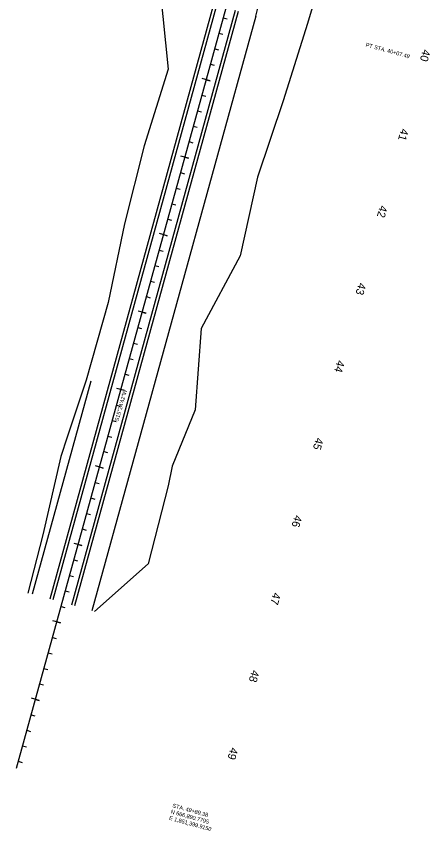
# Model space of a CAD drawing. Extents: x 1849567 to 1851966, y 666813 to 670457.
# Drawn here: x 1851400 to 1851915, y 666813 to 667827 of the extents above; entities that cross this region are included whole.
import ezdxf

# ---------------------------------------------------------------- set-up
doc = ezdxf.new("R2010")
doc.units = 0
for name, color, linetype in [('_CIVIL_CONSTRUCTION', 7, 'Continuous'), ('Default', 7, 'Continuous'), ('DES - CL - Proposed', 7, 'Continuous'), ('DES - CL - Proposed Curve Text', 7, 'Continuous'), ('DES - CL - Proposed Text', 7, 'Continuous'), ('DES - CL - Proposed Text - Large', 7, 'Continuous'), ('DES - CL - Proposed Text - Small', 7, 'Continuous'), ('DES - MODEL - Lines - Cut Slopes', 7, 'Continuous'), ('DES - MODEL - Lines - Ditch Centerline', 7, 'Continuous'), ('DES - MODEL - Lines - Pavement Edge', 7, 'Continuous'), ('DES - MODEL - Lines - Shoulder Edge', 7, 'Continuous')]:
    doc.layers.add(name, color=color, linetype=linetype)

msp = doc.modelspace()

# ---------------------------------------------------------------- linework, layer by layer
at = {"layer": '_CIVIL_CONSTRUCTION'}
msp.add_line((1851660.9, 667837.4), (1851399.9, 666890.8), dxfattribs=at)
at = {"layer": 'Default'}
msp.add_line((1851660.9, 667837.4), (1851399.9, 666890.8), dxfattribs=at)
msp.add_line((1851660.9, 667837.4), (1851399.9, 666890.8), dxfattribs=at)
at = {"layer": 'DES - CL - Proposed'}
msp.add_line((1851660.9, 667837.4), (1851399.9, 666890.8), dxfattribs=at)
at = {"layer": 'DES - CL - Proposed Text - Large'}
for p, q in [((1851636.3, 667748.2), (1851641.1, 667746.9)), ((1851636.3, 667748.2), (1851641.1, 667746.9)), ((1851609.7, 667651.8), (1851614.5, 667650.5)), ((1851609.7, 667651.8), (1851614.5, 667650.5)), ((1851583.1, 667555.4), (1851587.9, 667554)), ((1851583.1, 667555.4), (1851587.9, 667554)), ((1851556.5, 667459), (1851561.3, 667457.6)), ((1851556.5, 667459), (1851561.3, 667457.6)), ((1851534.8, 667361.2), (1851525.1, 667363.9)), ((1851534.8, 667361.2), (1851525.1, 667363.9)), ((1851503.4, 667266.2), (1851508.2, 667264.8)), ((1851503.4, 667266.2), (1851508.2, 667264.8)), ((1851476.8, 667169.8), (1851481.6, 667168.4)), ((1851476.8, 667169.8), (1851481.6, 667168.4)), ((1851450.2, 667073.4), (1851455, 667072)), ((1851450.2, 667073.4), (1851455, 667072)), ((1851423.7, 666976.9), (1851428.5, 666975.6)), ((1851423.7, 666976.9), (1851428.5, 666975.6))]:
    msp.add_line(p, q, dxfattribs=at)
at = {"layer": 'DES - CL - Proposed Text - Small'}
for p, q in [((1851657.5, 667825.3), (1851662.3, 667824)), ((1851657.5, 667825.3), (1851662.3, 667824)), ((1851652.2, 667806), (1851657, 667804.7)), ((1851652.2, 667806), (1851657, 667804.7)), ((1851646.9, 667786.7), (1851651.7, 667785.4)), ((1851646.9, 667786.7), (1851651.7, 667785.4)), ((1851641.6, 667767.5), (1851646.4, 667766.1)), ((1851641.6, 667767.5), (1851646.4, 667766.1)), ((1851641.1, 667746.9), (1851631.4, 667749.5)), ((1851641.1, 667746.9), (1851631.4, 667749.5)), ((1851631, 667728.9), (1851635.8, 667727.6)), ((1851631, 667728.9), (1851635.8, 667727.6)), ((1851625.6, 667709.6), (1851630.4, 667708.3)), ((1851625.6, 667709.6), (1851630.4, 667708.3)), ((1851620.3, 667690.3), (1851625.1, 667689)), ((1851620.3, 667690.3), (1851625.1, 667689)), ((1851615, 667671.1), (1851619.8, 667669.7)), ((1851615, 667671.1), (1851619.8, 667669.7)), ((1851614.5, 667650.4), (1851604.9, 667653.1)), ((1851614.5, 667650.4), (1851604.9, 667653.1)), ((1851604.4, 667632.5), (1851609.2, 667631.2)), ((1851604.4, 667632.5), (1851609.2, 667631.2)), ((1851599.1, 667613.2), (1851603.9, 667611.9)), ((1851599.1, 667613.2), (1851603.9, 667611.9)), ((1851593.7, 667593.9), (1851598.5, 667592.6)), ((1851593.7, 667593.9), (1851598.5, 667592.6)), ((1851588.4, 667574.7), (1851593.2, 667573.3)), ((1851588.4, 667574.7), (1851593.2, 667573.3)), ((1851587.9, 667554), (1851578.3, 667556.7)), ((1851587.9, 667554), (1851578.3, 667556.7)), ((1851577.8, 667536.1), (1851582.6, 667534.8)), ((1851577.8, 667536.1), (1851582.6, 667534.8)), ((1851572.5, 667516.8), (1851577.3, 667515.5)), ((1851572.5, 667516.8), (1851577.3, 667515.5)), ((1851567.2, 667497.5), (1851572, 667496.2)), ((1851567.2, 667497.5), (1851572, 667496.2)), ((1851561.9, 667478.2), (1851566.7, 667476.9)), ((1851561.9, 667478.2), (1851566.7, 667476.9)), ((1851561.4, 667457.6), (1851551.7, 667460.3)), ((1851561.4, 667457.6), (1851551.7, 667460.3)), ((1851551.2, 667439.7), (1851556, 667438.4)), ((1851551.2, 667439.7), (1851556, 667438.4)), ((1851545.9, 667420.4), (1851550.7, 667419.1)), ((1851545.9, 667420.4), (1851550.7, 667419.1)), ((1851540.6, 667401.1), (1851545.4, 667399.8)), ((1851540.6, 667401.1), (1851545.4, 667399.8)), ((1851535.3, 667381.8), (1851540.1, 667380.5)), ((1851535.3, 667381.8), (1851540.1, 667380.5)), ((1851534.8, 667361.2), (1851525.1, 667363.9)), ((1851534.8, 667361.2), (1851525.1, 667363.9)), ((1851524.7, 667343.3), (1851529.5, 667342)), ((1851524.7, 667343.3), (1851529.5, 667342)), ((1851519.3, 667324), (1851524.1, 667322.7)), ((1851519.3, 667324), (1851524.1, 667322.7)), ((1851514, 667304.7), (1851518.8, 667303.4)), ((1851514, 667304.7), (1851518.8, 667303.4)), ((1851508.7, 667285.4), (1851513.5, 667284.1)), ((1851508.7, 667285.4), (1851513.5, 667284.1)), ((1851508.2, 667264.8), (1851498.6, 667267.5)), ((1851508.2, 667264.8), (1851498.6, 667267.5)), ((1851498.1, 667246.9), (1851502.9, 667245.6)), ((1851498.1, 667246.9), (1851502.9, 667245.6)), ((1851492.8, 667227.6), (1851497.6, 667226.3)), ((1851492.8, 667227.6), (1851497.6, 667226.3)), ((1851487.4, 667208.3), (1851492.2, 667207)), ((1851487.4, 667208.3), (1851492.2, 667207)), ((1851482.1, 667189), (1851486.9, 667187.7)), ((1851482.1, 667189), (1851486.9, 667187.7)), ((1851481.6, 667168.4), (1851472, 667171.1)), ((1851481.6, 667168.4), (1851472, 667171.1)), ((1851471.5, 667150.5), (1851476.3, 667149.2)), ((1851471.5, 667150.5), (1851476.3, 667149.2)), ((1851466.2, 667131.2), (1851471, 667129.9)), ((1851466.2, 667131.2), (1851471, 667129.9)), ((1851460.9, 667111.9), (1851465.7, 667110.6)), ((1851460.9, 667111.9), (1851465.7, 667110.6)), ((1851455.6, 667092.6), (1851460.4, 667091.3)), ((1851455.6, 667092.6), (1851460.4, 667091.3)), ((1851455.1, 667072), (1851445.4, 667074.7)), ((1851455.1, 667072), (1851445.4, 667074.7)), ((1851444.9, 667054.1), (1851449.7, 667052.7)), ((1851444.9, 667054.1), (1851449.7, 667052.7)), ((1851439.6, 667034.8), (1851444.4, 667033.5)), ((1851439.6, 667034.8), (1851444.4, 667033.5)), ((1851434.3, 667015.5), (1851439.1, 667014.2)), ((1851434.3, 667015.5), (1851439.1, 667014.2)), ((1851429, 666996.2), (1851433.8, 666994.9)), ((1851429, 666996.2), (1851433.8, 666994.9)), ((1851428.5, 666975.6), (1851418.8, 666978.3)), ((1851428.5, 666975.6), (1851418.8, 666978.3)), ((1851418.4, 666957.7), (1851423.2, 666956.3)), ((1851418.4, 666957.7), (1851423.2, 666956.3)), ((1851413, 666938.4), (1851417.8, 666937.1)), ((1851413, 666938.4), (1851417.8, 666937.1)), ((1851407.7, 666919.1), (1851412.5, 666917.8)), ((1851407.7, 666919.1), (1851412.5, 666917.8)), ((1851402.4, 666899.8), (1851407.2, 666898.5)), ((1851402.4, 666899.8), (1851407.2, 666898.5))]:
    msp.add_line(p, q, dxfattribs=at)
at = {"layer": 'DES - MODEL - Lines - Cut Slopes'}
for points in [[(1851579.2, 667859.9), (1851589, 667761.2), (1851559.2, 667665.7), (1851534.6, 667568.8), (1851514.2, 667470.7), (1851486.9, 667374.4), (1851463.3, 667303.2), (1851455.2, 667279.4), (1851432.8, 667181.9), (1851414.4, 667109.2)], [(1851768.1, 667837.5), (1851762.3, 667818.3), (1851759.8, 667810.1), (1851732.3, 667721.7), (1851700, 667626.9), (1851678.8, 667529), (1851630.2, 667438.7), (1851622.4, 667337.1), (1851594.1, 667267.1), (1851588.9, 667242.6), (1851564.2, 667145.7), (1851497.1, 667086.4)]]:
    msp.add_lwpolyline(points, dxfattribs=at)
at = {"layer": 'DES - MODEL - Lines - Ditch Centerline'}
for p, q in [((1851698, 667827.1), (1851494, 667087.2)), ((1851492.8, 667372.8), (1851419.8, 667107.7))]:
    msp.add_line(p, q, dxfattribs=at)
msp.add_arc((1850433.4, 668175.7), 1311.8, 344.5884, 349.4254, dxfattribs=at)
at = {"layer": 'DES - MODEL - Lines - Pavement Edge'}
for p, q in [((1851649.3, 667840.6), (1851445.3, 667100.6)), ((1851672.4, 667834.2), (1851468.5, 667094.3))]:
    msp.add_line(p, q, dxfattribs=at)
at = {"layer": 'DES - MODEL - Lines - Shoulder Edge'}
for p, q in [((1851645.4, 667841.6), (1851441.5, 667101.7)), ((1851676.3, 667833.1), (1851472.3, 667093.2))]:
    msp.add_line(p, q, dxfattribs=at)

# ---------------------------------------------------------------- texts
at = {"layer": 'DES - CL - Proposed Curve Text'}
for s, p in [('PT', (1851834.4, 667789.5)), ('PT', (1851834.4, 667789.5)), (' STA. ', (1851843, 667787.2)), (' STA. ', (1851843, 667787.2)), ('40+07.49', (1851861.1, 667782.2)), ('40+07.49', (1851861.1, 667782.2))]:
    msp.add_text(s, height=4.98, rotation=344.5884, dxfattribs=at).set_placement(p)
at = {"layer": 'DES - CL - Proposed Text'}
for s, rotation, p in [('S15°24\'42"W', 74.5884, (1851527.2, 667322.5)), ('S15°24\'42"W', 74.5884, (1851527.2, 667322.5)), ('STA. ', 344.5884, (1851593.9, 666842.6)), ('STA. ', 344.5884, (1851593.9, 666842.6)), ('N ', 344.5884, (1851591.8, 666835)), ('N ', 344.5884, (1851591.8, 666835)), ('666,890.7795', 344.5884, (1851598.5, 666833.1)), ('666,890.7795', 344.5884, (1851598.5, 666833.1)), ('49+89.38', 344.5884, (1851610.2, 666838.1)), ('49+89.38', 344.5884, (1851610.2, 666838.1)), ('E ', 344.5884, (1851589.7, 666827.3)), ('E ', 344.5884, (1851589.7, 666827.3)), ('1,851,399.9150', 344.5884, (1851596, 666825.5)), ('1,851,399.9150', 344.5884, (1851596, 666825.5))]:
    msp.add_text(s, height=4.98, rotation=rotation, dxfattribs=at).set_placement(p)
at = {"layer": 'DES - CL - Proposed Text - Large'}
for s, rotation, p in [('40', 254.9255, (1851906.1, 667786.7)), ('40', 254.9255, (1851906.1, 667786.7)), ('45', 254.5884, (1851773, 667303.3)), ('45', 254.5884, (1851773, 667303.3))]:
    msp.add_text(s, height=9.96, rotation=rotation, dxfattribs=at).set_placement(p)
at = {"layer": 'DES - CL - Proposed Text - Small'}
for s, rotation, p in [('40', 254.9255, (1851906.1, 667786.7)), ('40', 254.9255, (1851906.1, 667786.7)), ('41', 254.5884, (1851879, 667688)), ('41', 254.5884, (1851879, 667688)), ('42', 254.5884, (1851852.7, 667592.4)), ('42', 254.5884, (1851852.7, 667592.4)), ('43', 254.5884, (1851826.1, 667496.1)), ('43', 254.5884, (1851826.1, 667496.1)), ('44', 254.5884, (1851799.5, 667399.7)), ('44', 254.5884, (1851799.5, 667399.7)), ('45', 254.5884, (1851773, 667303.3)), ('45', 254.5884, (1851773, 667303.3)), ('46', 254.5884, (1851746.4, 667206.9)), ('46', 254.5884, (1851746.4, 667206.9)), ('47', 254.5884, (1851719.8, 667110.5)), ('47', 254.5884, (1851719.8, 667110.5)), ('48', 254.5884, (1851693.2, 667014.1)), ('48', 254.5884, (1851693.2, 667014.1)), ('49', 254.5884, (1851666.7, 666917.7)), ('49', 254.5884, (1851666.7, 666917.7))]:
    msp.add_text(s, height=9.96, rotation=rotation, dxfattribs=at).set_placement(p)

doc.saveas('drawing.dxf')
